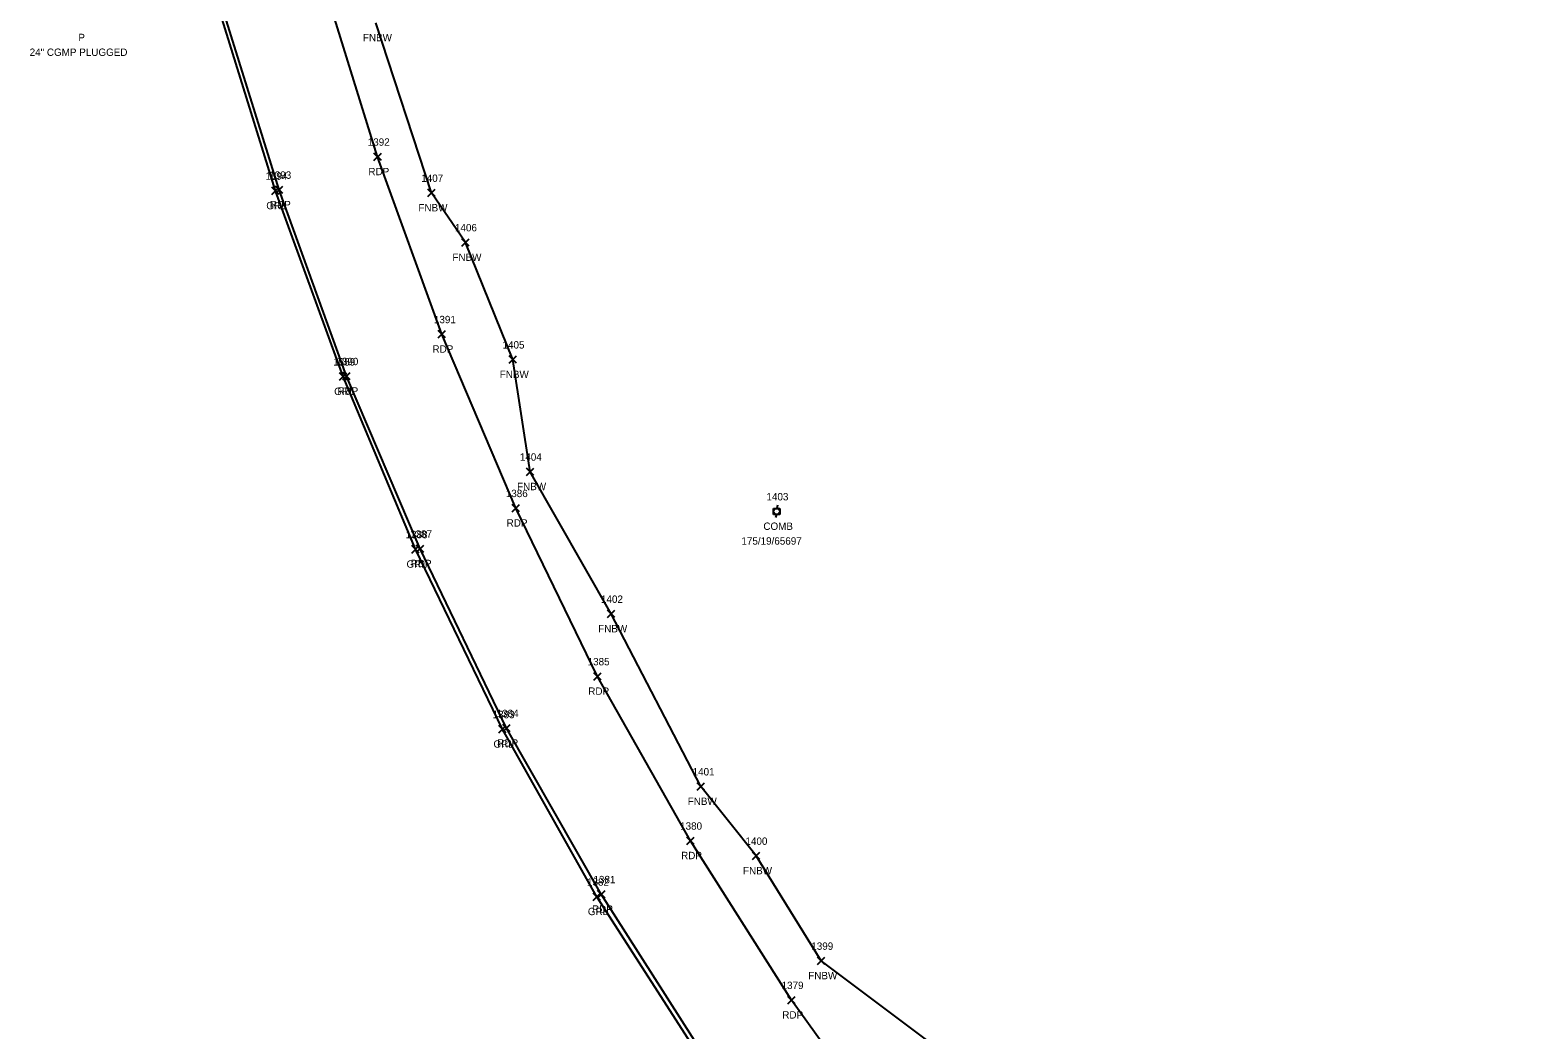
# Model space of a CAD drawing. Extents: x 1503463 to 1505240, y 712171 to 717196.
# Drawn here: x 1503552.6 to 1503961.3, y 715621.6 to 715892.8 of the extents above; entities that cross this region are included whole.
import ezdxf

# ---------------------------------------------------------------- set-up
doc = ezdxf.new("R2010")
doc.units = 0
for name, color, linetype in [('D_A', 7, 'Continuous'), ('D_C', 7, 'Continuous'), ('L_A', 7, 'Continuous'), ('L_I', 7, 'Continuous'), ('L_TIC', 7, 'Continuous'), ('LFNC', 7, 'Continuous'), ('P_A', 7, 'Continuous'), ('P_I', 7, 'Continuous'), ('P_TIC', 7, 'Continuous'), ('PET', 7, 'Continuous'), ('R_A', 7, 'Continuous'), ('R_I', 7, 'Continuous'), ('R_TIC', 7, 'Continuous'), ('RGR', 7, 'Continuous'), ('U_A', 7, 'Continuous'), ('U_C', 7, 'Continuous'), ('U_I', 7, 'Continuous'), ('UP', 7, 'Continuous')]:
    doc.layers.add(name, color=color, linetype=linetype)

msp = doc.modelspace()

# ---------------------------------------------------------------- linework, layer by layer
at = {"layer": 'L_TIC'}
for points in [[(1503660.34, 715847.63), (1503662.34, 715849.63)], [(1503662.34, 715847.63), (1503660.34, 715849.63)], [(1503669.55, 715834.21), (1503671.55, 715836.21)], [(1503671.55, 715834.21), (1503669.55, 715836.21)], [(1503682.38, 715802.43), (1503684.38, 715804.43)], [(1503684.38, 715802.43), (1503682.38, 715804.43)], [(1503687.07, 715772.01), (1503689.07, 715774.01)], [(1503689.07, 715772.01), (1503687.07, 715774.01)], [(1503709.07, 715733.45), (1503711.07, 715735.45)], [(1503711.07, 715733.45), (1503709.07, 715735.45)], [(1503733.34, 715686.63), (1503735.34, 715688.63)], [(1503735.34, 715686.63), (1503733.34, 715688.63)], [(1503748.33, 715667.81), (1503750.33, 715669.81)], [(1503750.33, 715667.81), (1503748.33, 715669.81)], [(1503766.01, 715639.34), (1503768.01, 715641.34)], [(1503768.01, 715639.34), (1503766.01, 715641.34)]]:
    msp.add_lwpolyline(points, dxfattribs=at)
at = {"layer": 'LFNC'}
msp.add_lwpolyline([(1503928.04, 715461.57), (1503892.3, 715500.86), (1503865.48, 715532.69), (1503827.53, 715573.6), (1503806.72, 715610.49), (1503767.01, 715640.34), (1503749.33, 715668.81), (1503734.34, 715687.63), (1503710.07, 715734.45), (1503688.07, 715773.01), (1503683.38, 715803.43), (1503670.55, 715835.21), (1503661.34, 715848.63), (1503646.28, 715894.79)], dxfattribs=at)
at = {"layer": 'P_TIC'}
for points in [[(1503645.76, 715857.44), (1503647.76, 715859.44)], [(1503647.76, 715857.44), (1503645.76, 715859.44)], [(1503619.07, 715848.48), (1503621.07, 715850.48)], [(1503621.07, 715848.48), (1503619.07, 715850.48)], [(1503663.14, 715809.3), (1503665.14, 715811.3)], [(1503665.14, 715809.3), (1503663.14, 715811.3)], [(1503637.35, 715797.92), (1503639.35, 715799.92)], [(1503639.35, 715797.92), (1503637.35, 715799.92)], [(1503683.24, 715762.13), (1503685.24, 715764.13)], [(1503685.24, 715762.13), (1503683.24, 715764.13)], [(1503657.24, 715751.13), (1503659.24, 715753.13)], [(1503659.24, 715751.13), (1503657.24, 715753.13)], [(1503705.38, 715716.5), (1503707.38, 715718.5)], [(1503707.38, 715716.5), (1503705.38, 715718.5)], [(1503680.7, 715702.45), (1503682.7, 715704.45)], [(1503682.7, 715702.45), (1503680.7, 715704.45)], [(1503730.53, 715671.92), (1503732.53, 715673.92)], [(1503732.53, 715671.92), (1503730.53, 715673.92)], [(1503706.39, 715657.39), (1503708.39, 715659.39)], [(1503708.39, 715657.39), (1503706.39, 715659.39)], [(1503757.96, 715628.69), (1503759.96, 715630.69)], [(1503759.96, 715628.69), (1503757.96, 715630.69)]]:
    msp.add_lwpolyline(points, dxfattribs=at)
at = {"layer": 'PET'}
for points in [[(1504086.6, 715320.97), (1504048.23, 715348.08), (1504021.82, 715368.03), (1503966.17, 715409.92), (1503923.82, 715445.68), (1503891.58, 715474.62), (1503849.62, 715517.03), (1503813.69, 715557.19), (1503785.7, 715592.4), (1503758.96, 715629.69), (1503731.53, 715672.92), (1503706.38, 715717.5), (1503684.24, 715763.13), (1503664.14, 715810.3), (1503646.76, 715858.44), (1503630.24, 715911.59)], [(1504010.26, 715341.79), (1503951.37, 715387.03), (1503906.51, 715423.33), (1503870.54, 715455.93), (1503828.42, 715498.53), (1503793.3, 715537.68), (1503762.47, 715576.59), (1503736.04, 715613.53), (1503707.39, 715658.39), (1503681.7, 715703.45), (1503658.24, 715752.13), (1503638.35, 715798.92), (1503620.07, 715849.48), (1503602.71, 715905.3)]]:
    msp.add_lwpolyline(points, dxfattribs=at)
at = {"layer": 'R_TIC'}
for points in [[(1503618.03, 715848.2), (1503620.03, 715850.2)], [(1503620.03, 715848.2), (1503618.03, 715850.2)], [(1503636.42, 715797.81), (1503638.42, 715799.81)], [(1503638.42, 715797.81), (1503636.42, 715799.81)], [(1503656.03, 715750.97), (1503658.03, 715752.97)], [(1503658.03, 715750.97), (1503656.03, 715752.97)], [(1503679.6, 715702.16), (1503681.6, 715704.16)], [(1503681.6, 715702.16), (1503679.6, 715704.16)], [(1503705.21, 715656.74), (1503707.21, 715658.74)], [(1503707.21, 715656.74), (1503705.21, 715658.74)]]:
    msp.add_lwpolyline(points, dxfattribs=at)
at = {"layer": 'RGR'}
msp.add_lwpolyline([(1503947.53, 715382.87), (1503905.72, 715422.63), (1503869.81, 715454.98), (1503827.55, 715497.64), (1503792.71, 715537), (1503761.83, 715576.02), (1503735.02, 715612.85), (1503706.21, 715657.74), (1503680.6, 715703.16), (1503657.03, 715751.97), (1503637.42, 715798.81), (1503619.03, 715849.2), (1503601.73, 715905.18)], dxfattribs=at)
at = {"layer": 'UP'}
for p, q in [((1503754.1, 715761.41), (1503754.1, 715763.07)), ((1503754.1, 715763.07), (1503755.77, 715763.07)), ((1503755.18, 715763.91), (1503754.93, 715763.07)), ((1503754.93, 715762.24), (1503754.93, 715762.24)), ((1503755.77, 715763.07), (1503755.77, 715761.41)), ((1503755.77, 715761.41), (1503754.1, 715761.41)), ((1503754.68, 715760.57), (1503754.93, 715761.41))]:
    msp.add_line(p, q, dxfattribs=at)
msp.add_circle((1503754.93, 715762.24), 0.833, dxfattribs=at)

# ---------------------------------------------------------------- texts
at = {"layer": 'D_A'}
msp.add_text('P', height=2, dxfattribs=at).set_placement((1503565.63, 715889.81))
at = {"layer": 'D_C'}
msp.add_text('24" CGMP PLUGGED', height=2, dxfattribs=at).set_placement((1503552.42, 715885.81))
at = {"layer": 'L_A'}
for p in [(1503642.76, 715889.79), (1503657.81, 715843.63), (1503667.02, 715830.21), (1503679.85, 715798.43), (1503684.55, 715768.01), (1503706.54, 715729.45), (1503730.81, 715682.63), (1503745.8, 715663.81), (1503763.49, 715635.34)]:
    msp.add_text('FNBW', height=2, dxfattribs=at).set_placement(p)
at = {"layer": 'L_I'}
for s, p in [('1407', (1503658.57, 715851.63)), ('1406', (1503667.72, 715838.21)), ('1405', (1503680.61, 715806.43)), ('1404', (1503685.3, 715776.01)), ('1402', (1503707.3, 715737.45)), ('1401', (1503732.14, 715690.63)), ('1400', (1503746.47, 715671.81)), ('1399', (1503764.31, 715643.34))]:
    msp.add_text(s, height=2, dxfattribs=at).set_placement(p)
at = {"layer": 'P_A'}
for p in [(1503644.25, 715853.44), (1503617.56, 715844.48), (1503661.62, 715805.3), (1503635.84, 715793.92), (1503681.73, 715758.13), (1503655.73, 715747.13), (1503703.86, 715712.5), (1503679.19, 715698.45), (1503729.02, 715667.92), (1503704.88, 715653.39), (1503756.45, 715624.69)]:
    msp.add_text('RDP', height=2, dxfattribs=at).set_placement(p)
at = {"layer": 'P_I'}
for s, p in [('1392', (1503644.07, 715861.44)), ('1393', (1503617.38, 715852.48)), ('1391', (1503662.01, 715813.3)), ('1390', (1503635.57, 715801.92)), ('1386', (1503681.49, 715766.13)), ('1387', (1503655.54, 715755.13)), ('1385', (1503703.68, 715720.5)), ('1384', (1503679.01, 715706.45)), ('1380', (1503728.75, 715675.92)), ('1381', (1503705.27, 715661.39)), ('1379', (1503756.26, 715632.69))]:
    msp.add_text(s, height=2, dxfattribs=at).set_placement(p)
at = {"layer": 'R_A'}
for p in [(1503616.57, 715844.2), (1503634.96, 715793.81), (1503654.58, 715746.97), (1503678.15, 715698.16), (1503703.75, 715652.74)]:
    msp.add_text('GRL', height=2, dxfattribs=at).set_placement(p)
at = {"layer": 'R_I'}
for s, p in [('1394', (1503616.33, 715852.2)), ('1389', (1503634.72, 715801.81)), ('1388', (1503654.34, 715754.97)), ('1383', (1503677.91, 715706.16)), ('1382', (1503703.52, 715660.74))]:
    msp.add_text(s, height=2, dxfattribs=at).set_placement(p)
at = {"layer": 'U_A'}
msp.add_text('COMB', height=2, dxfattribs=at).set_placement((1503751.32, 715757.24))
at = {"layer": 'U_C'}
msp.add_text('175/19/65697', height=2, dxfattribs=at).set_placement((1503745.37, 715753.24))
at = {"layer": 'U_I'}
msp.add_text('1403', height=2, dxfattribs=at).set_placement((1503752.16, 715765.24))

doc.saveas('drawing.dxf')
